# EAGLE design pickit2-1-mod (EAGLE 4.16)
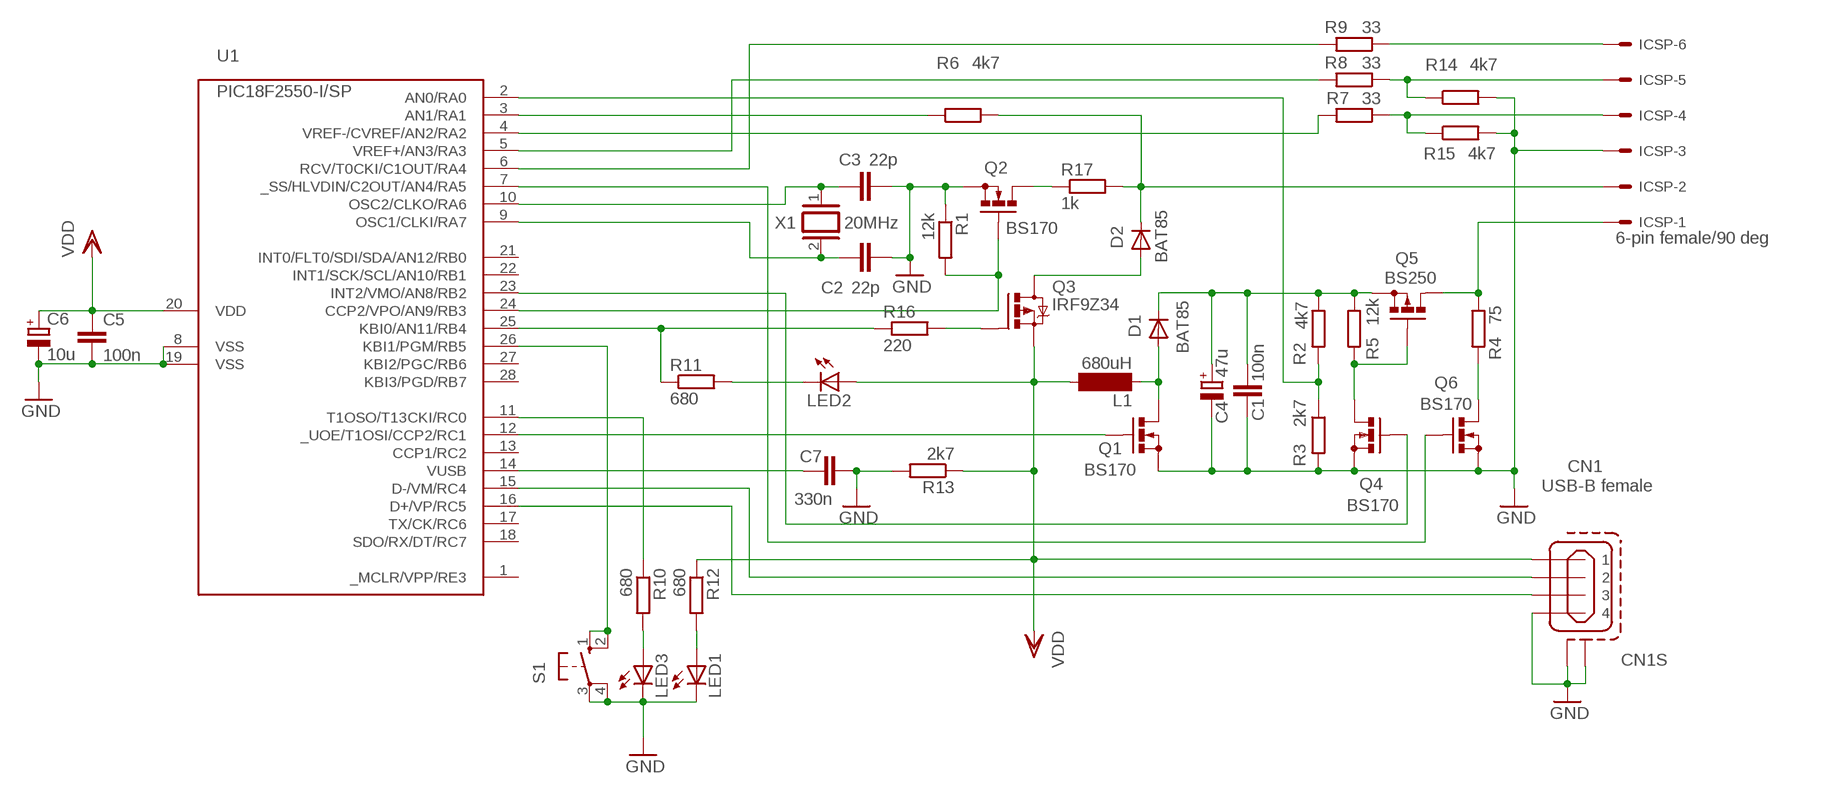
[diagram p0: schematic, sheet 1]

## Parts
C1  100n  C-EU050-025X075  [C050-025X075]
C2  22p  C-EU025-024X044  [C025-024X044]
C3  22p  C-EU025-024X044  [C025-024X044]
C4  47u  CPOL-EUE2.5-5  [E2,5-5]
C5  100n  C-EU050-025X075  [C050-025X075]
C6  10u  CPOL-EUE2.5-5  [E2,5-5]
C7  330n  C-EU050-025X075  [C050-025X075]
CN1  USB-B female  MINI-USB_SHIELD4P-85-32004-00X  [85-32004-00X]
D1  BAT85  BAT81  [DO34-7]
D2  BAT85  BAT81  [DO34-7]
ICSP  6-pin female/90 deg  22-05-7068-06  [7395-06]
L1  680uH  BS11  [BS11]
LED1  LED3MM  [LED3MM]
LED2  LED3MM  [LED3MM]
LED3  LED3MM  [LED3MM]
Q1  BS170  [SOT54E]
Q2  BS170  [SOT54E]
Q3  IRF9Z34  IRF9530  [TO220BV]
Q4  BS170  [SOT54E]
Q5  BS250  [SOT54E]
Q6  BS170  [SOT54E]
R1  12k  R-EU_0204/5  [0204/5]
R2  4k7  R-EU_0204/5  [0204/5]
R3  2k7  R-EU_0204/5  [0204/5]
R4  75  R-EU_0204/5  [0204/5]
R5  12k  R-EU_0204/5  [0204/5]
R6  4k7  R-EU_0204/5  [0204/5]
R7  33  R-EU_0204/5  [0204/5]
R8  33  R-EU_0204/5  [0204/5]
R9  33  R-EU_0204/5  [0204/5]
R10  680  R-EU_0204/5  [0204/5]
R11  680  R-EU_0204/5  [0204/5]
R12  680  R-EU_0204/5  [0204/5]
R13  2k7  R-EU_0204/5  [0204/5]
R14  4k7  R-EU_0204/5  [0204/5]
R15  4k7  R-EU_0204/5  [0204/5]
R16  220  R-EU_0204/5  [0204/5]
R17  1k  R-EU_0204/5  [0204/5]
S1  10-XX  [B3F-10XX]
U1  PIC18F2550-I/SP  [DIL28-3]
X1  20MHz  XTAL/S  [QS]

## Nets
GND: C1.2 C2.2 C3.2 C4.- C5.2 C6.- C7.2 CN1.4 CN1.M1(S1) CN1.M2(S2) ICSP.3 LED1.K(C) LED3.K(C) Q1.S Q2.S Q4.S Q6.S R1.1 R3.2 R13.2 R14.2 R15.2 S1.3(P) S1.4(P1) U1.8(VSS) U1.19(VSS)
N$1: C3.1 U1.10(OSC2/CLKO/RA6) X1.1
N$2: C2.1 U1.9(OSC1/CLKI/RA7) X1.2
N$3: D1.A L1.1 Q1.D
N$4: Q1.G U1.12(_UOE/T1OSI/CCP2/RC1)
N$5: C1.1 C4.+ D1.C Q5.S R2.1 R5.1
N$6: R11.1 R16.1 U1.25(KBI0/AN11/RB4)
N$7: D2.C ICSP.2 R6.2 R17.2
N$8: LED1.A R12.2
N$9: R2.2 R3.1 U1.2(AN0/RA0)
N$10: Q4.D Q5.G R5.2
N$11: Q6.D R4.2
N$12: ICSP.1 Q5.D R4.1
N$13: Q6.G U1.7(_SS/HLVDIN/C2OUT/AN4/RA5)
N$14: Q4.G U1.23(INT2/VMO/AN8/RB2)
N$15: R6.1 U1.3(AN1/RA1)
N$16: ICSP.6 R9.1
N$17: ICSP.5 R8.1 R14.1
N$18: ICSP.4 R7.1 R15.1
N$19: R7.2 U1.4(VREF-/CVREF/AN2/RA2)
N$20: R8.2 U1.5(VREF+/AN3/RA3)
N$21: R9.2 U1.6(RCV/T0CKI/C1OUT/RA4)
N$22: C7.1 U1.14(VUSB)
N$23: LED2.K(C) R11.2
N$24: D2.A Q3.D
N$25: CN1.2 U1.15(D-/VM/RC4)
N$26: CN1.3 U1.16(D+/VP/RC5)
N$27: Q3.G R16.2
N$28: Q2.G R1.2 U1.24(CCP2/VPO/AN9/RB3)
N$29: LED3.A R10.2
N$30: R10.1 U1.11(T1OSO/T13CKI/RC0)
N$31: Q2.D R17.1
N$32: S1.1(S) S1.2(S1) U1.26(KBI1/PGM/RB5)
VDD: C5.1 C6.+ CN1.1 L1.2 LED2.A Q3.S R12.1 R13.1 U1.20(VDD)
Unconnected: U1.1(_MCLR/VPP/RE3) U1.13(CCP1/RC2) U1.17(TX/CK/RC6) U1.18(SDO/RX/DT/RC7) U1.21(INT0/FLT0/SDI/SDA/AN12/RB0) U1.22(INT1/SCK/SCL/AN10/RB1) U1.27(KBI2/PGC/RB6) U1.28(KBI3/PGD/RB7)

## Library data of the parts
C1-C3 C5 C7 = rcl:C-EU: CAPACITOR, European symbol
C4 C6 = rcl:CPOL-EU: POLARIZED CAPACITOR, European symbol
CN1 = con-cypressindustries:MINI-USB_SHIELD4P-: MINI USB 4 Pol. Source: www.cypressindustries.com
D1 D2 = diode:BAT81: DIODE
ICSP = con-molex:22-?-06: CONNECTOR wire to board 2.54 mm (.1 inch) pitch header
L1 = inductor-neosid:BS: INDUCTOR
LED1-LED3 = led:LED: LED
Q1 Q2 Q4 Q6 = transistor-small-signal:BS170: N-CHANNEL MOS FET
Q3 = transistor-power:IRF9530: P-CHANNEL HEXFET POWER-MOS-FET Source: http://www.irf.com/product-info/datasheets/data/irf9530.pdf
Q5 = transistor-small-signal:BS250: P-CHANNEL MOS FET
R1-R17 = rcl:R-EU_: RESISTOR, European symbol
S1 = switch-omron:10-XX: OMRON SWITCH
U1 = microchip-pic18fxx5x:PIC18*2550: PIC18*2550 Microchip FLASH Microcontroller with FS-USB DEVICE FEATURES FeaturePIC18*2550 Program Memory (bytes) 32k Program Memory (instructions) 16384 I/O Ports Ports A, B, C, (E) Capture/Compare/PWM Modules 2 Enhanced Capture/Compare/PWM Modules 0 Parallel Communications (PSP) No 10-bit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
X1 = special:XTAL/S: CRYSTAL

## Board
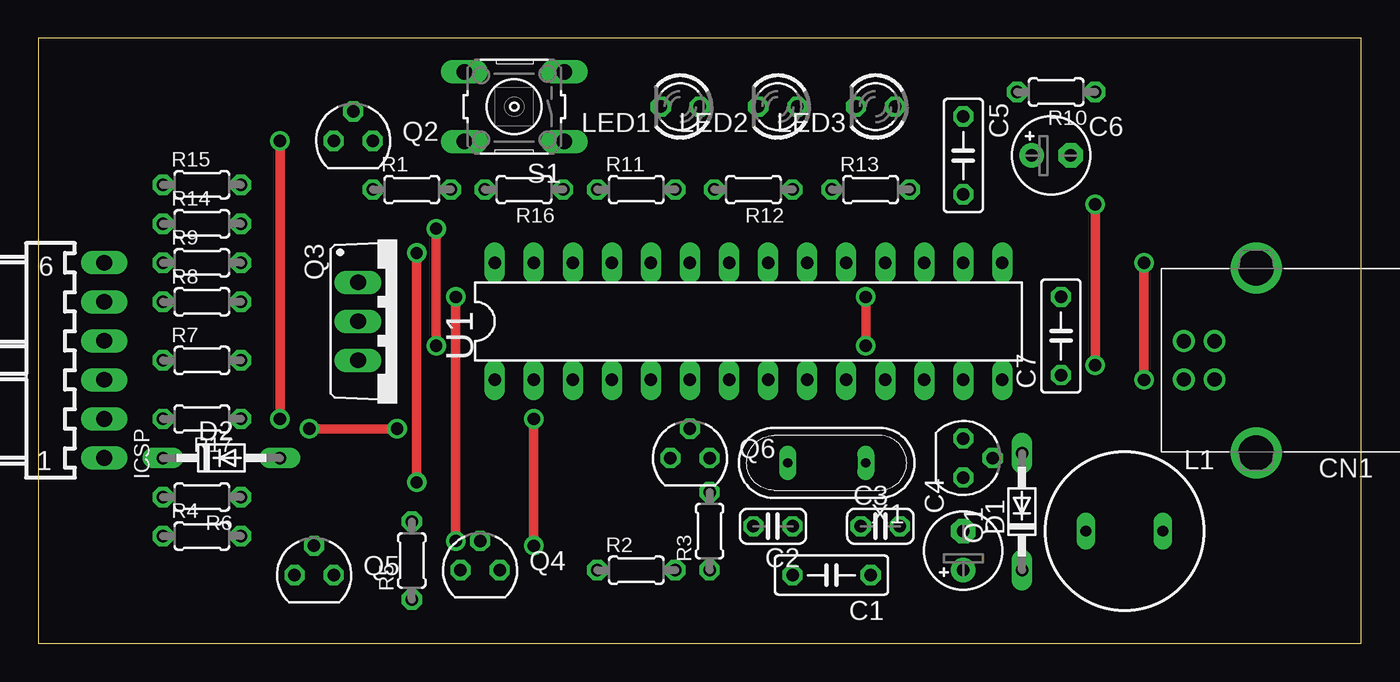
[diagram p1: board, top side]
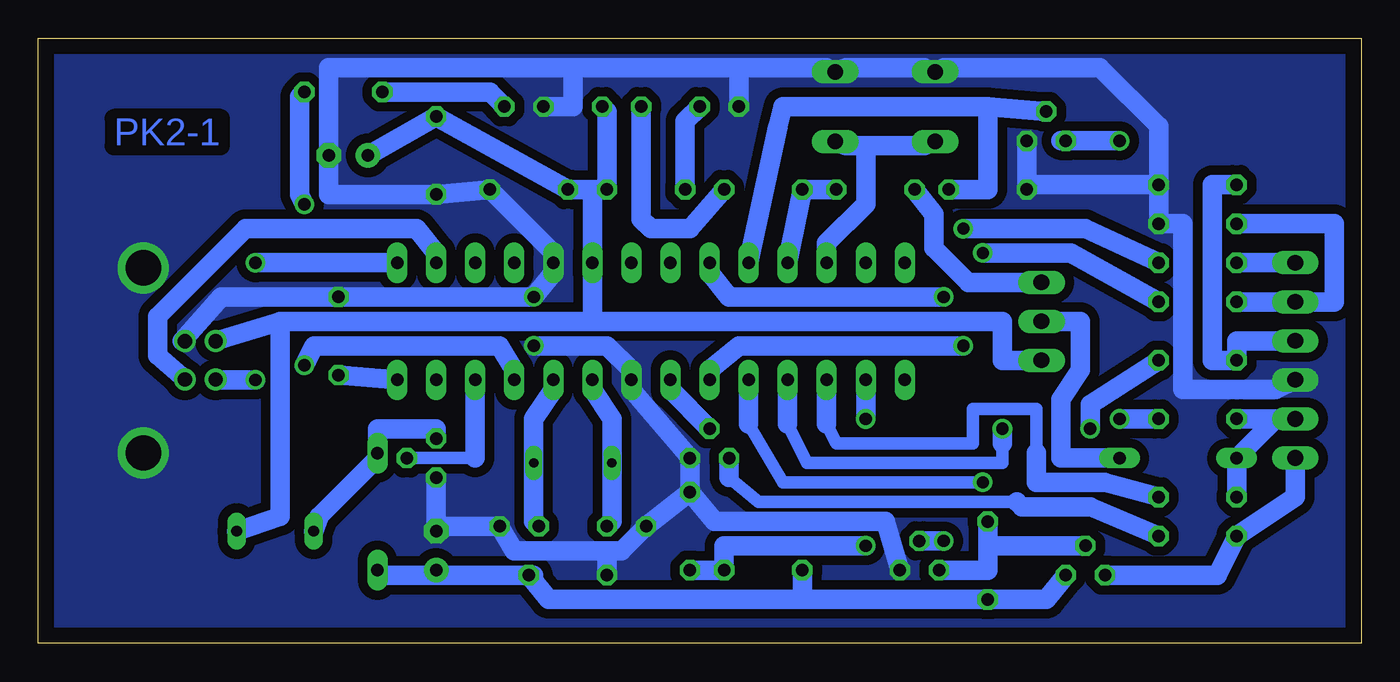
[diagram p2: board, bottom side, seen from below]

Size 86.03 x 39.36 mm. Coordinates in mm from the lower left corner, seen from the top.
Outline: 0,0 86.03,0 86.03,39.36 0,39.36 0,0
Copper layers (1*16): Top 0.035mm / dielectric 1.5mm / Bottom 0.035mm
Design rules "default": minimum track width 10mil, minimum drill 24mil, track to track 8mil, track to pad 8mil, pad to pad 8mil, via to via 8mil, smd to smd 8mil, copper to edge 40mil, drill to drill 8mil, minimum pad ring 10mil, minimum via ring 8mil, stop-mask expansion 4mil, vias tented up to drill 0mil, thermal gap 10mil

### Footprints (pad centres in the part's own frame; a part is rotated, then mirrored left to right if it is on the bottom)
C050-025X075 = drill 0.813 octagon: 1 -2.54,0; 2 2.54,0
C025-024X044 = drill 0.813 octagon: 1 -1.27,0; 2 1.27,0
E2,5-5 = drill 0.813 pad 1.6 round: + -1.27,0 | drill 0.813 pad 1.6 octagon: - 1.27,0
85-32004-00X = drill 0.92 pad 1.27 round: 1 4.71,-1.25; 2 4.71,1.25; 3 2.71,1.25; 4 2.71,-1.25 | drill 2.3 pad 3 round: M1 0,6.02; M2 0,-6.02
DO34-7 = drill 0.813 long: A 3.81,0; C -3.81,0
7395-06 = drill 1.016 long: 1 6.35,0; 2 3.81,0; 3 1.27,0; 4 -1.27,0; 5 -3.81,0; 6 -6.35,0
BS11 = drill 0.7 long: 1 -2.5,0; 2 2.5,0
LED3MM = drill 0.813 octagon: A -1.27,0; K 1.27,0
SOT54E = drill 0.813 octagon: D -1.27,0; G 0,1.905; S 1.27,0
TO220BV = drill 1.016 long: D 0,-2.54; G -2.54,-2.54; S 2.54,-2.54
0204/5 = drill 0.813 octagon: 1 -2.54,0; 2 2.54,0
B3F-10XX = drill 1.016 long: 1 -3.251,2.261; 2 3.251,2.261; 3 -3.251,-2.261; 4 3.251,-2.261
DIL28-3 = drill 0.813 long: 1 -16.51,-3.81; 2 -13.97,-3.81; 3 -11.43,-3.81; 4 -8.89,-3.81; 5 -6.35,-3.81; 6 -3.81,-3.81; 7 -1.27,-3.81; 8 1.27,-3.81; 9 3.81,-3.81; 10 6.35,-3.81; 11 8.89,-3.81; 12 11.43,-3.81; 13 13.97,-3.81; 14 16.51,-3.81; 15 16.51,3.81; 16 13.97,3.81; 17 11.43,3.81; 18 8.89,3.81; 19 6.35,3.81; 20 3.81,3.81; 21 1.27,3.81; 22 -1.27,3.81; 23 -3.81,3.81; 24 -6.35,3.81; 25 -8.89,3.81; 26 -11.43,3.81; 27 -13.97,3.81; 28 -16.51,3.81
QS = drill 0.61 long: 1 -2.54,0; 2 2.54,0

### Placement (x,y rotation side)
C1  51.59,4.44 180 top
C2  47.78,7.61 180 top
C3  54.76,7.61 0 top
C4  60.16,6.03 90 top
C5  60.16,31.75 270 top
C6  65.88,31.75 0 top
C7  66.51,20 90 top
CN1  79.21,18.41 180 top
D1  63.97,8.57 90 top
D2  11.9,12.06 0 top
ICSP  4.28,18.41 270 top
L1  70.64,7.3 0 top
LED1  41.74,34.92 180 top
LED2  48.09,34.92 180 top
LED3  54.44,34.92 180 top
Q1  60.16,12.06 270 top
Q2  20.47,32.7 0 top
Q3  23.33,20.95 270 top
Q4  28.73,4.76 0 top
Q5  17.93,4.44 0 top
Q6  42.38,12.06 0 top
R1  24.28,29.52 0 top
R2  38.89,4.76 0 top
R3  43.65,7.3 90 top
R4  10.63,6.98 0 top
R5  24.28,5.39 90 top
R6  10.63,9.52 180 top
R7  10.63,18.41 0 top
R8  10.63,22.22 0 top
R9  10.63,24.76 0 top
R10  66.19,35.87 180 top
R11  38.89,29.52 0 top
R12  46.51,29.52 180 top
R13  54.13,29.52 0 top
R14  10.63,27.3 0 top
R15  10.63,29.84 0 top
R16  31.59,29.52 180 top
R17  10.63,14.6 180 top
S1  30.95,34.92 180 top
U1  46.19,20.95 0 top
X1  51.27,11.74 180 top

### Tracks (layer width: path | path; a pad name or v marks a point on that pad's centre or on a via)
GND  (via drill 0.8 pad 1.27)
  Top 0.61: v53.81,22.54 v53.81,19.36
  Bottom 0.406: 21.74,29.84 R1.1
  Bottom 1.27: Q1.S C4.- 60.16,7.61 C3.2 55.08,6.03 49.05,6.03 | 49.05,6.03 C1.2 | 76.67,19.68 74.13,22.54 C7.2 v53.81,22.54 52.54,24.12 U1.19 52.54,25.39 R13.2 C5.2 67.14,29.21 C6.- 67.14,37.46 51.27,37.46 | R15.2 R14.2 11.58,27.3 11.58,16.5 5.55,16.5 ICSP.3 | Q6.S 47.46,16.5 U1.8 47.46,17.77 49.05,19.36 v53.81,19.36 | Q6.S R3.2 | R3.2 C2.2 48.09,6.03 49.05,6.03 | Q6.S R3.2 | Q6.S R3.2 | R3.2 42.06,7.93 30.95,7.93 Q4.S | 40.48,37.46 34.76,37.46 S1.3 33.49,37.46 28.41,37.46 S1.4 27.14,37.46 16.98,37.46 13.17,33.65 R15.2 | LED3.K 51.27,34.92 51.27,37.46 | 40.48,37.46 LED1.K | 40.48,37.46 51.27,37.46 | R15.2 21.74,29.84 Q2.S
  pour Bottom (isolate 0.61, no thermals): 0.15,39.36 0.15,-0.01 85.88,-0.01 85.88,39.36
N$1
  Bottom 1.27: U1.10 52.54,16.5 53.81,14.6 X1.1 53.81,7.93 C3.1
N$2
  Bottom 1.27: U1.9 50,16.5 48.73,14.6 X1.2 48.73,7.93 C2.1
N$3
  Bottom 1.27: L1.1 67.78,8.25 63.97,12.06 D1.A 63.97,13.96 60.16,13.96 Q1.D
N$4
  Bottom 0.813: 57.62,12.06 Q1.G
  Bottom 1.27: 57.62,12.06 U1.12
N$5
  Bottom 1.27: C1.1 52.86,2.85 36.35,2.85 | 36.35,2.85 R5.1 20.47,2.85 Q5.S | 60.16,4.44 63.97,4.44 D1.C | C1.1 60.16,4.44 | 60.16,4.44 C4.+ | C1.1 53.81,4.44 | 36.35,2.85 R2.1
N$6
  Bottom 1.27: U1.25 R11.1 R16.1
N$7
  Bottom 1.27: R6.2 D2.C 5.55,14.6 ICSP.2 R17.2
N$8
  Bottom 1.27: R12.2 43.97,33.97 LED1.A
N$9  (via drill 0.8 pad 1.27)
  Top 0.61: v32.22,6.34 v32.22,14.6
  Bottom 1.27: R2.2 R3.1 R2.2 | R2.2 41.43,6.34 v32.22,6.34 | v32.22,14.6 U1.2
N$10
  Bottom 1.27: Q5.G 24.28,6.34 | Q4.D 24.28,4.76 24.28,6.34 | 24.28,6.34 R5.2
N$11
  Bottom 0.813: 22.38,9.2 39.2,9.2 41.11,10.79
  Bottom 1.27: R4.2 17.61,8.88 22.06,8.88 22.38,9.2 | 41.11,10.79 Q6.D
N$12
  Bottom 1.27: ICSP.1 4.28,9.52 R4.1 9.36,4.44 Q5.D
N$13
  Bottom 1.27: Q6.G 44.92,16.5 U1.7
N$14  (via drill 0.8 pad 1.27)
  Top 0.61: v27.14,6.66 v27.14,22.54
  Bottom 1.27: v27.14,22.54 41.11,22.54 42.38,24.12 U1.23 | Q4.G v27.14,6.66
N$15
  Bottom 0.813: 21.11,12.38 21.11,15.23 25.23,15.23 25.23,13.01 34.12,13.01 34.76,14.28
  Bottom 1.27: R6.1 16.66,10.47 21.11,10.47 21.11,12.38 | 34.76,14.28 U1.3
N$16
  Bottom 1.27: ICSP.6 R9.1
N$17
  Bottom 1.27: R8.1 ICSP.5 1.74,22.22 1.74,27.3 R14.1
N$18
  Bottom 1.27: ICSP.4 8.09,19.68 R7.1 9.68,18.41 9.68,29.84 R15.1
N$19  (via drill 0.8 pad 1.27)
  Top 0.61: v17.61,13.96 v23.33,13.96
  Bottom 0.813: 23.33,13.01 23.33,11.74 36.03,11.74 37.3,14.28
  Bottom 1.27: R7.2 17.61,15.55 v17.61,13.96 | v23.33,13.96 23.33,13.01 | 37.3,14.28 U1.4
N$20  (via drill 0.8 pad 1.27)
  Top 0.61: v24.6,25.39 v24.6,10.47
  Bottom 0.813: v24.6,10.47 37.62,10.47 39.84,14.28
  Bottom 1.27: R8.2 18.88,25.39 v24.6,25.39 | 39.84,14.28 U1.5
N$21  (via drill 0.8 pad 1.27)
  Top 0.61: v25.87,26.98 v25.87,19.36
  Bottom 1.27: v25.87,26.98 17.93,26.98 R9.2 | U1.6 42.38,17.77 40.48,19.36 v25.87,19.36
N$22
  Bottom 1.27: U1.14 C7.1
N$23
  Bottom 1.27: R11.2 43.65,26.98 46.19,26.98 46.83,27.62 LED2.K
N$24
  Bottom 1.27: D2.A 19.52,12.06 19.52,15.87 18.25,17.77 18.25,20.95 Q3.D
N$25  (via drill 0.8 pad 1.27)
  Top 0.61: v71.91,24.76 v71.91,17.14
  Bottom 1.27: U1.15 v71.91,24.76 | CN1.2 74.45,17.14 v71.91,17.14
N$26
  Bottom 1.27: U1.16 60.16,25.39 61.43,26.98 72.54,26.98 78.26,21.27 78.26,18.73 CN1.3
N$27
  Bottom 1.27: R16.2 27.77,27.93 27.77,25.71 25.55,23.49 Q3.G
N$28
  Bottom 1.27: 24.28,34.92 24.28,29.52 R1.2 | 24.28,34.92 37.62,34.92 37.94,33.65 U1.24 | 24.28,34.92 Q2.G
N$29
  Bottom 1.27: LED3.A 56.67,35.87 R10.2
N$30  (via drill 0.8 pad 1.27)
  Top 0.61: v68.73,18.09 v68.73,28.57
  Bottom 1.27: v68.73,18.09 68.1,19.36 56.03,19.36 55.08,17.77 U1.11 | v68.73,28.57 69.05,29.21 69.05,35.55 R10.1
N$31  (via drill 0.8 pad 1.27)
  Top 0.61: v15.71,14.6 v15.71,32.7
  Bottom 0.406: Q2.D 19.52,32.7 19.52,32.38
  Bottom 1.27: R17.1 v15.71,14.6 | v15.71,32.7 19.52,32.7
N$32
  Bottom 1.27: 32.22,32.38 28.41,32.38 S1.2 | 32.22,32.38 33.49,32.38 S1.1 | 32.22,32.38 32.22,28.57 34.76,26.03 U1.26
VDD
  Bottom 1.27: L1.2 70.32,8.25 70.32,20.95 | 50,20.95 U1.20 50,29.52 | 50,20.95 70.32,20.95 | C6.+ C5.1 R13.1 50,29.52 | 50,29.52 R12.1 49.05,34.6 LED2.A | 50,20.95 23.33,20.95 23.33,18.41 Q3.S | 70.32,20.95 CN1.1

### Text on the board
Bottom: PK2-1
